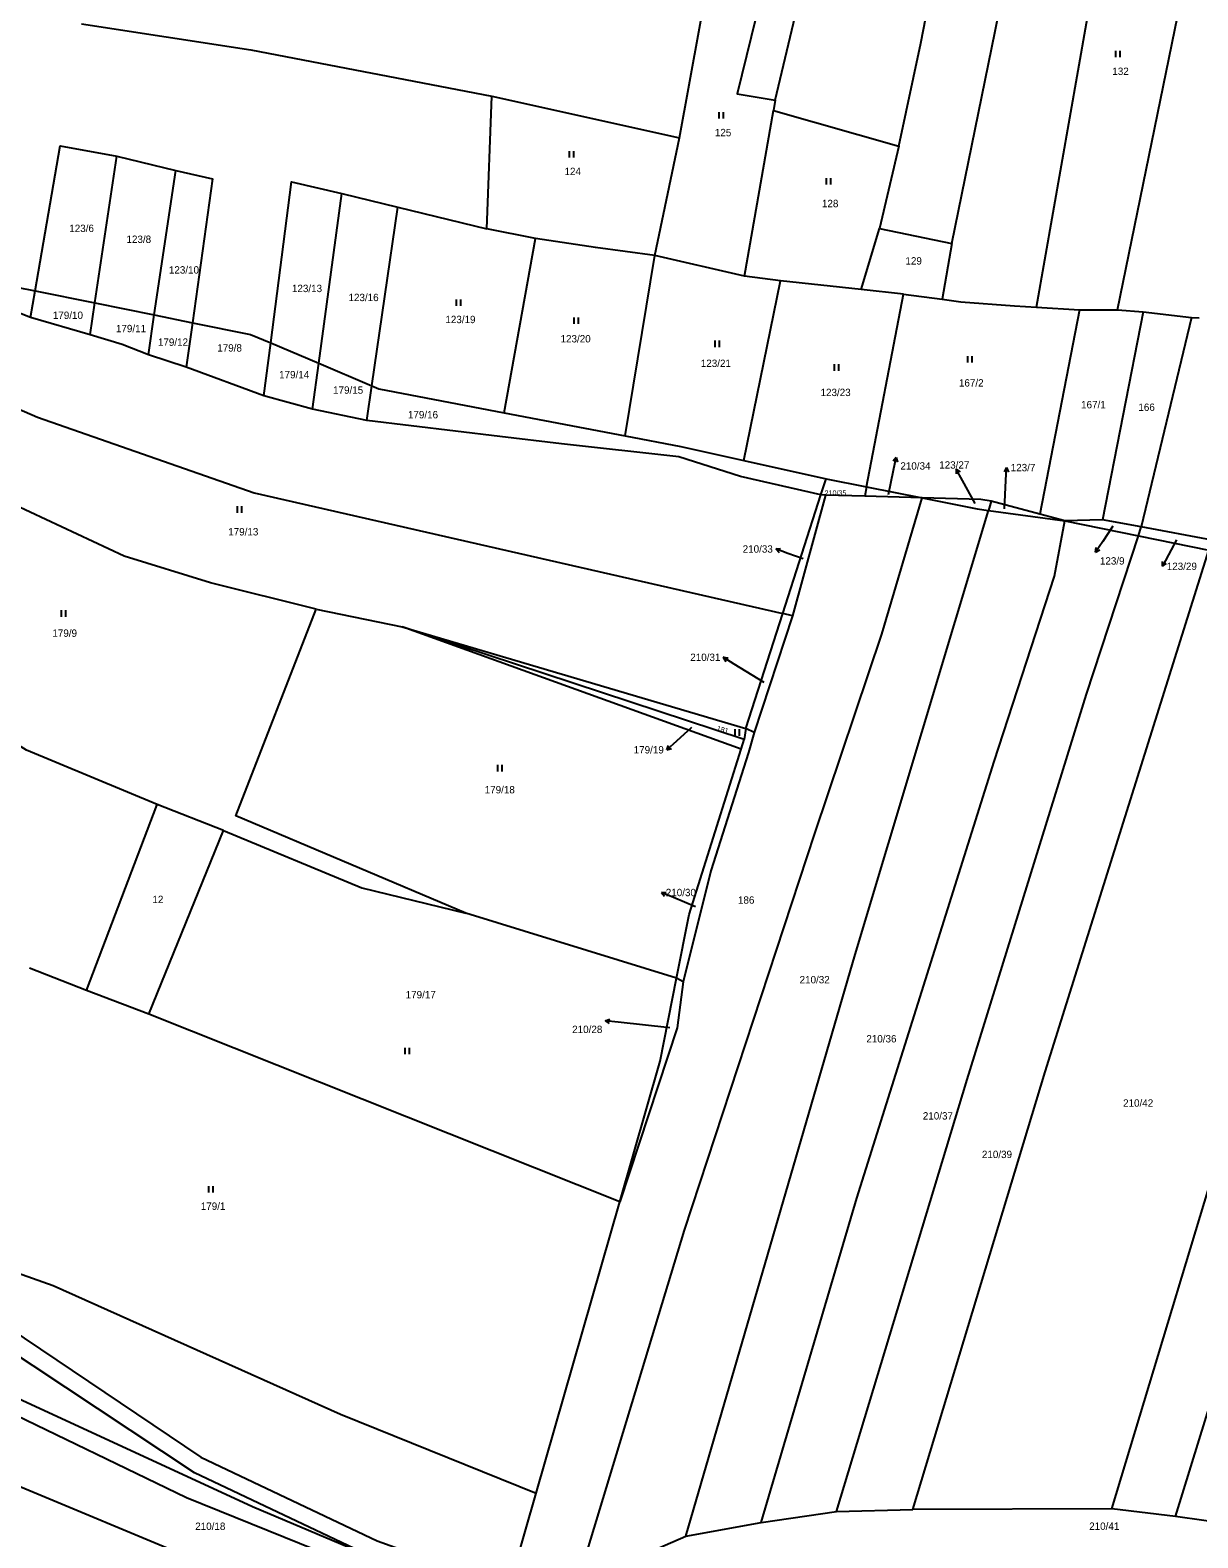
# Model space of a CAD drawing. Extents: x -746176 to -739709, y -1128407 to -1124482.
# Drawn here: x -742743.6 to -742474.2, y -1127693.8 to -1127345.9 of the extents above; entities that cross this region are included whole.
import ezdxf

# ---------------------------------------------------------------- set-up
doc = ezdxf.new("R2010")
doc.units = 0
for name, color, linetype in [('Vrstva 33', 7, 'Continuous'), ('Vrstva 42', 7, 'Continuous'), ('Vrstva 43', 7, 'Continuous'), ('Vrstva 44', 7, 'Continuous')]:
    doc.layers.add(name, color=color, linetype=linetype)

msp = doc.modelspace()

# ---------------------------------------------------------------- linework, layer by layer
at = {"layer": 'Vrstva 33'}
for p, q in [((-742638.23, -1127391.73), (-742637.04, -1127361.12)), ((-742637.04, -1127361.12), (-742593.77, -1127370.76)), ((-742578.78, -1127402.69), (-742572.09, -1127364.45)), ((-742571.73, -1127362.05), (-742572.09, -1127364.45)), ((-742572.09, -1127364.45), (-742543.19, -1127372.64)), ((-742599.43, -1127397.9), (-742593.77, -1127370.76)), ((-742728.68, -1127408.84), (-742723.61, -1127374.95)), ((-742723.61, -1127374.95), (-742709.98, -1127378.27)), ((-742543.19, -1127372.64), (-742547.67, -1127391.65)), ((-742714.95, -1127411.61), (-742709.98, -1127378.27)), ((-742677.01, -1127422.76), (-742671.68, -1127383.55)), ((-742671.68, -1127383.55), (-742658.73, -1127386.75)), ((-742664.74, -1127427.96), (-742658.73, -1127386.75)), ((-742658.73, -1127386.75), (-742638.23, -1127391.73)), ((-742626.99, -1127394), (-742638.23, -1127391.73)), ((-742551.9, -1127405.77), (-742547.67, -1127391.65)), ((-742547.67, -1127391.65), (-742530.91, -1127395.09)), ((-742634.26, -1127434.17), (-742626.99, -1127394)), ((-742530.91, -1127395.09), (-742533.18, -1127408)), ((-742743.5, -1127412.2), (-742776.69, -1127399.15)), ((-742776.69, -1127399.15), (-742742.44, -1127406.06)), ((-742606.32, -1127439.53), (-742599.43, -1127397.9)), ((-742578.78, -1127402.69), (-742599.43, -1127397.9)), ((-742570.47, -1127403.73), (-742578.78, -1127402.69)), ((-742743.5, -1127412.2), (-742742.44, -1127406.06)), ((-742742.44, -1127406.06), (-742728.68, -1127408.84)), ((-742578.95, -1127445.21), (-742570.47, -1127403.73)), ((-742551.9, -1127405.77), (-742570.47, -1127403.73)), ((-742542.09, -1127406.85), (-742551.9, -1127405.77)), ((-742550.64, -1127451.27), (-742542.09, -1127406.85)), ((-742542.09, -1127406.85), (-742533.18, -1127408)), ((-742729.77, -1127416.16), (-742728.68, -1127408.84)), ((-742728.68, -1127408.84), (-742714.95, -1127411.61)), ((-742511.41, -1127409.84), (-742501.5, -1127410.43)), ((-742501.5, -1127410.43), (-742510.66, -1127457.59)), ((-742501.5, -1127410.43), (-742492.74, -1127410.43)), ((-742492.74, -1127410.43), (-742486.8, -1127410.88)), ((-742729.77, -1127416.16), (-742743.5, -1127412.2)), ((-742716.31, -1127420.78), (-742714.95, -1127411.61)), ((-742714.95, -1127411.61), (-742706.16, -1127413.39)), ((-742706.16, -1127413.39), (-742707.61, -1127423.69)), ((-742486.8, -1127410.88), (-742496.21, -1127458.9)), ((-742475.67, -1127412.21), (-742487.24, -1127460.49)), ((-742486.8, -1127410.88), (-742475.67, -1127412.21)), ((-742475.67, -1127412.21), (-742473.87, -1127412.26)), ((-742707.61, -1127423.69), (-742716.31, -1127420.78)), ((-742689.66, -1127430.29), (-742688.08, -1127418.07)), ((-742688.08, -1127418.07), (-742677.01, -1127422.76)), ((-742689.66, -1127430.29), (-742707.61, -1127423.69)), ((-742678.44, -1127433.32), (-742677.01, -1127422.76)), ((-742677.01, -1127422.76), (-742664.74, -1127427.96)), ((-742678.44, -1127433.32), (-742689.66, -1127430.29)), ((-742665.91, -1127435.97), (-742664.74, -1127427.96)), ((-742665.91, -1127435.97), (-742678.44, -1127433.32)), ((-742634.26, -1127434.17), (-742606.32, -1127439.53)), ((-742578.95, -1127445.21), (-742559.94, -1127449.42)), ((-742561.14, -1127453.13), (-742559.94, -1127449.42)), ((-742559.94, -1127449.42), (-742550.64, -1127451.27)), ((-742550.64, -1127451.27), (-742551.05, -1127453.42)), ((-742550.64, -1127451.27), (-742537.81, -1127453.81)), ((-742569.95, -1127480.48), (-742561.14, -1127453.13)), ((-742560.06, -1127453.16), (-742567.73, -1127481)), ((-742560.06, -1127453.16), (-742561.14, -1127453.13)), ((-742551.05, -1127453.42), (-742560.06, -1127453.16)), ((-742537.81, -1127453.81), (-742551.05, -1127453.42)), ((-742521.86, -1127454.6), (-742522.49, -1127456.7)), ((-742510.66, -1127457.59), (-742521.86, -1127454.6)), ((-742522.49, -1127456.7), (-742504.84, -1127459.15)), ((-742504.84, -1127459.15), (-742510.66, -1127457.59)), ((-742496.21, -1127458.9), (-742504.84, -1127459.15)), ((-742504.84, -1127459.15), (-742487.9, -1127462.57)), ((-742487.24, -1127460.49), (-742496.21, -1127458.9)), ((-742487.9, -1127462.57), (-742487.24, -1127460.49)), ((-742487.9, -1127462.57), (-742471.63, -1127465.86)), ((-742470.92, -1127463.6), (-742487.24, -1127460.49)), ((-742677.58, -1127479.48), (-742657.78, -1127483.59)), ((-742578.5, -1127507.04), (-742569.95, -1127480.48)), ((-742567.73, -1127481), (-742576.53, -1127507.95)), ((-742567.73, -1127481), (-742569.95, -1127480.48)), ((-742657.78, -1127483.59), (-742578.5, -1127507.04)), ((-742579.56, -1127511.82), (-742657.78, -1127483.59)), ((-742578.86, -1127509.59), (-742657.78, -1127483.59)), ((-742578.5, -1127507.04), (-742578.86, -1127509.59)), ((-742576.53, -1127507.95), (-742578.5, -1127507.04)), ((-742579.56, -1127511.82), (-742578.86, -1127509.59)), ((-742730.61, -1127567.49), (-742714.26, -1127524.61)), ((-742699.01, -1127530.54), (-742714.26, -1127524.61)), ((-742716.21, -1127572.93), (-742699.01, -1127530.54)), ((-742594.44, -1127564.65), (-742643.07, -1127549.64)), ((-742730.61, -1127567.49), (-742743.76, -1127562.35)), ((-742592.94, -1127565.49), (-742594.44, -1127564.65)), ((-742716.21, -1127572.93), (-742730.61, -1127567.49)), ((-742607.54, -1127616.24), (-742716.21, -1127572.93)), ((-742626.86, -1127683.46), (-742607.54, -1127616.24)), ((-742632.48, -1127703.04), (-742626.86, -1127683.46)), ((-742574.91, -1127690.26), (-742557.53, -1127687.75)), ((-742557.53, -1127687.75), (-742539.98, -1127687.22)), ((-742494, -1127687.08), (-742539.98, -1127687.22)), ((-742479.32, -1127688.85), (-742494, -1127687.08)), ((-742592.33, -1127693.42), (-742574.91, -1127690.26)), ((-742464.41, -1127690.97), (-742479.32, -1127688.85)), ((-742617.34, -1127704.25), (-742592.33, -1127693.42))]:
    msp.add_line(p, q, dxfattribs=at)
for points in [[(-742571.73, -1127362.05), (-742565.58, -1127336.15), (-742554.25, -1127280.44), (-742551.83, -1127272.48)], [(-742543.19, -1127372.64), (-742538.11, -1127348.86), (-742526.83, -1127290.76), (-742523.05, -1127277.11)], [(-742530.91, -1127395.09), (-742510.84, -1127296.63), (-742506.04, -1127280.03)], [(-742511.41, -1127409.84), (-742497.94, -1127333.24), (-742489.37, -1127297.91), (-742486.41, -1127283.7)], [(-742492.74, -1127410.43), (-742471.55, -1127307.03), (-742467.25, -1127290.58)], [(-742593.77, -1127370.76), (-742586.78, -1127332.31), (-742583.12, -1127305.02)], [(-742582.72, -1127303.04), (-742570.71, -1127320.74), (-742580.44, -1127360.6), (-742571.73, -1127362.05)], [(-742731.72, -1127344.4), (-742692.68, -1127350.41), (-742637.04, -1127361.12)], [(-742742.44, -1127406.06), (-742736.64, -1127372.59), (-742723.61, -1127374.95)], [(-742709.98, -1127378.27), (-742701.49, -1127380.16), (-742706.16, -1127413.39)], [(-742688.08, -1127418.07), (-742683.29, -1127380.91), (-742671.68, -1127383.55)], [(-742599.43, -1127397.9), (-742613.15, -1127396.01), (-742626.99, -1127394)], [(-742533.18, -1127408), (-742528.9, -1127408.56), (-742516.49, -1127409.54), (-742511.41, -1127409.84)], [(-742706.16, -1127413.39), (-742692.72, -1127416.1), (-742688.08, -1127418.07)], [(-742716.31, -1127420.78), (-742722.38, -1127418.4), (-742729.77, -1127416.16)], [(-742782.56, -1127417.54), (-742741.92, -1127435.21), (-742691.94, -1127452.67), (-742569.95, -1127480.48)], [(-742664.74, -1127427.96), (-742663.18, -1127428.62), (-742634.26, -1127434.17)], [(-742677.58, -1127479.48), (-742701.98, -1127473.41), (-742721.92, -1127467.25), (-742790.61, -1127435.15)], [(-742561.14, -1127453.13), (-742579.7, -1127448.86), (-742593.95, -1127444.37), (-742621, -1127441.33), (-742635.25, -1127439.62), (-742665.91, -1127435.97)], [(-742606.32, -1127439.53), (-742593.44, -1127442), (-742578.95, -1127445.21)], [(-742617.34, -1127704.25), (-742592.59, -1127622.78), (-742562.59, -1127531.26), (-742547.11, -1127485.27), (-742537.81, -1127453.81)], [(-742521.86, -1127454.6), (-742524.23, -1127454.21), (-742537.81, -1127453.81)], [(-742537.81, -1127453.81), (-742525.12, -1127456.33), (-742522.49, -1127456.7)], [(-742592.33, -1127693.42), (-742553.24, -1127559.15), (-742522.49, -1127456.7)], [(-742574.91, -1127690.26), (-742552.84, -1127615.42), (-742521.15, -1127514.67), (-742507.28, -1127471.86), (-742504.84, -1127459.15)], [(-742557.53, -1127687.75), (-742527.44, -1127588.04), (-742499.87, -1127499.13), (-742487.9, -1127462.57)], [(-742539.98, -1127687.22), (-742509.38, -1127586.29), (-742471.63, -1127465.86)], [(-742494, -1127687.08), (-742463.97, -1127587.54), (-742428.89, -1127476.24)], [(-742643.07, -1127549.64), (-742696.11, -1127527.15), (-742677.58, -1127479.48)], [(-742479.32, -1127688.85), (-742461.68, -1127631.58), (-742415.87, -1127480.36)], [(-742714.26, -1127524.61), (-742744.44, -1127512), (-742789.88, -1127483.77)], [(-742576.53, -1127507.95), (-742577.87, -1127512.58), (-742586.52, -1127539.9), (-742592.94, -1127565.49)], [(-742594.44, -1127564.65), (-742591.53, -1127549.93), (-742579.56, -1127511.82)], [(-742699.01, -1127530.54), (-742667.09, -1127543.83), (-742643.07, -1127549.64)], [(-742607.54, -1127616.24), (-742598.22, -1127583.8), (-742594.44, -1127564.65)], [(-742592.94, -1127565.49), (-742594.28, -1127576.09), (-742607.54, -1127616.24)], [(-742842.01, -1127594.12), (-742781.53, -1127620.27), (-742738.25, -1127635.58), (-742671.97, -1127665.27), (-742626.86, -1127683.46)], [(-742849.54, -1127613.47), (-742848.76, -1127613.6), (-742786.4, -1127635.17), (-742756.11, -1127640.29), (-742704.21, -1127675.14), (-742663.56, -1127694.46), (-742647.49, -1127700.26), (-742632.48, -1127703.04)], [(-742664.42, -1127698.33), (-742705.7, -1127678.8), (-742757.77, -1127644.27), (-742759.53, -1127644.48)], [(-742763.36, -1127654.17), (-742748.4, -1127660.64), (-742692.32, -1127686.56), (-742664.42, -1127698.33)], [(-742640.13, -1127711.82), (-742707.48, -1127684.6), (-742751.48, -1127663.32), (-742764.73, -1127657.63)], [(-742643.36, -1127725.63), (-742711.98, -1127696.17), (-742770.35, -1127671.87)]]:
    msp.add_lwpolyline(points, dxfattribs=at)
at = {"layer": 'Vrstva 43'}
for p, q in [((-742543.8, -1127444.48), (-742544.49, -1127445.35)), ((-742544.42, -1127447.41), (-742543.8, -1127444.48)), ((-742543.8, -1127444.48), (-742543.51, -1127445.56)), ((-742545.56, -1127453.02), (-742544.42, -1127447.41)), ((-742528.52, -1127449.81), (-742529.97, -1127447.19)), ((-742529.97, -1127447.19), (-742529.05, -1127447.82)), ((-742529.97, -1127447.19), (-742529.93, -1127448.3)), ((-742518.34, -1127446.83), (-742518.9, -1127447.81)), ((-742518.5, -1127449.83), (-742518.34, -1127446.83)), ((-742518.34, -1127446.83), (-742517.9, -1127447.86)), ((-742525.6, -1127455.12), (-742528.52, -1127449.81)), ((-742518.79, -1127456.34), (-742518.5, -1127449.83)), ((-742493.78, -1127460.36), (-742496.13, -1127463.88)), ((-742571.59, -1127465.59), (-742570.48, -1127465.47)), ((-742568.77, -1127466.62), (-742571.59, -1127465.59)), ((-742571.59, -1127465.59), (-742570.82, -1127466.41)), ((-742496.13, -1127463.88), (-742497.81, -1127466.37)), ((-742497.81, -1127466.37), (-742497.66, -1127465.26)), ((-742497.81, -1127466.37), (-742496.83, -1127465.82)), ((-742479.13, -1127463.5), (-742480.96, -1127466.96)), ((-742565.23, -1127467.88), (-742568.77, -1127466.62)), ((-742480.96, -1127466.96), (-742482.37, -1127469.61)), ((-742482.37, -1127469.61), (-742482.34, -1127468.49)), ((-742482.37, -1127469.61), (-742481.46, -1127468.96)), ((-742581.13, -1127492.18), (-742583.68, -1127490.59)), ((-742583.68, -1127490.59), (-742582.56, -1127490.7)), ((-742583.68, -1127490.59), (-742583.09, -1127491.54)), ((-742574.26, -1127496.44), (-742581.13, -1127492.18)), ((-742590.98, -1127506.8), (-742594.5, -1127509.95)), ((-742594.5, -1127509.95), (-742596.73, -1127511.96)), ((-742596.73, -1127511.96), (-742596.32, -1127510.92)), ((-742596.73, -1127511.96), (-742595.65, -1127511.66)), ((-742597.94, -1127544.88), (-742596.83, -1127544.81)), ((-742595.18, -1127546.05), (-742597.94, -1127544.88)), ((-742597.94, -1127544.88), (-742597.22, -1127545.73)), ((-742590.09, -1127548.19), (-742595.18, -1127546.05)), ((-742610.93, -1127574.5), (-742609.88, -1127574.1)), ((-742607.94, -1127574.81), (-742610.93, -1127574.5)), ((-742610.93, -1127574.5), (-742609.98, -1127575.1)), ((-742596.01, -1127576.14), (-742607.94, -1127574.81))]:
    msp.add_line(p, q, dxfattribs=at)
at = {"layer": 'Vrstva 44'}
for p, q in [((-742493.1, -1127352.13), (-742493.1, -1127350.63)), ((-742492.1, -1127352.13), (-742492.1, -1127350.63)), ((-742584.6, -1127366.28), (-742584.6, -1127364.78)), ((-742583.6, -1127366.28), (-742583.6, -1127364.78)), ((-742619.18, -1127375.28), (-742619.18, -1127373.78)), ((-742618.18, -1127375.28), (-742618.18, -1127373.78)), ((-742559.87, -1127381.51), (-742559.87, -1127380.01)), ((-742558.87, -1127381.51), (-742558.87, -1127380.01)), ((-742645.22, -1127409.53), (-742645.22, -1127408.03)), ((-742644.22, -1127409.53), (-742644.22, -1127408.03)), ((-742618.06, -1127413.66), (-742618.06, -1127412.16)), ((-742617.06, -1127413.66), (-742617.06, -1127412.16)), ((-742585.52, -1127419.01), (-742585.52, -1127417.51)), ((-742584.52, -1127419.01), (-742584.52, -1127417.51)), ((-742558.05, -1127424.5), (-742558.05, -1127423)), ((-742557.05, -1127424.5), (-742557.05, -1127423)), ((-742527.22, -1127422.61), (-742527.22, -1127421.11)), ((-742526.22, -1127422.61), (-742526.22, -1127421.11)), ((-742695.72, -1127457.24), (-742695.72, -1127455.74)), ((-742694.72, -1127457.24), (-742694.72, -1127455.74)), ((-742736.33, -1127481.24), (-742736.33, -1127479.74)), ((-742735.33, -1127481.24), (-742735.33, -1127479.74)), ((-742580.97, -1127508.69), (-742580.97, -1127507.19)), ((-742579.97, -1127508.69), (-742579.97, -1127507.19)), ((-742635.71, -1127516.94), (-742635.71, -1127515.44)), ((-742634.71, -1127516.94), (-742634.71, -1127515.44)), ((-742657.03, -1127582.2), (-742657.03, -1127580.7)), ((-742656.03, -1127582.2), (-742656.03, -1127580.7)), ((-742702.33, -1127614.12), (-742702.33, -1127612.62)), ((-742701.33, -1127614.12), (-742701.33, -1127612.62))]:
    msp.add_line(p, q, dxfattribs=at)

# ---------------------------------------------------------------- texts
at = {"layer": 'Vrstva 42'}
for s, height, p in [('132', 1.7, (-742493.92, -1127356.23)), ('125', 1.7, (-742585.62, -1127370.37)), ('124', 1.7, (-742620.31, -1127379.33)), ('128', 1.7, (-742560.91, -1127386.74)), ('123/6', 1.7, (-742734.56, -1127392.47)), ('123/8', 1.7, (-742721.36, -1127394.99)), ('129', 1.7, (-742541.65, -1127399.98)), ('123/10', 1.7, (-742711.58, -1127402.06)), ('123/13', 1.7, (-742683.19, -1127406.34)), ('123/16', 1.7, (-742670.14, -1127408.42)), ('179/10', 1.7, (-742738.35, -1127412.53)), ('179/11', 1.7, (-742723.79, -1127415.59)), ('123/19', 1.7, (-742647.79, -1127413.5)), ('179/12', 1.7, (-742714.11, -1127418.73)), ('123/20', 1.7, (-742621.22, -1127417.95)), ('179/8', 1.7, (-742700.42, -1127420.06)), ('123/21', 1.7, (-742588.86, -1127423.61)), ('179/14', 1.7, (-742686.15, -1127426.23)), ('167/2', 1.7, (-742529.31, -1127428.13)), ('179/15', 1.7, (-742673.7, -1127429.79)), ('123/23', 1.7, (-742561.24, -1127430.33)), ('167/1', 1.7, (-742501.13, -1127433.16)), ('179/16', 1.7, (-742656.43, -1127435.47)), ('166', 1.7, (-742487.91, -1127433.75)), ('123/27', 1.7, (-742533.86, -1127447.07)), ('210/34', 1.7, (-742542.82, -1127447.3)), ('123/7', 1.7, (-742517.36, -1127447.68)), ('210/35', 1.19, (-742560.3, -1127453.27)), ('179/13', 1.7, (-742697.89, -1127462.49)), ('210/33', 1.7, (-742579.2, -1127466.46)), ('123/9', 1.7, (-742496.79, -1127469.21)), ('123/29', 1.7, (-742481.36, -1127470.46)), ('179/9', 1.7, (-742738.46, -1127485.88)), ('210/31', 1.7, (-742591.29, -1127491.45)), ('179/19', 1.7, (-742604.35, -1127512.8)), ('179/18', 1.7, (-742638.72, -1127522.01)), ('12', 1.7, (-742715.38, -1127547.33)), ('210/30', 1.7, (-742596.94, -1127545.73)), ('186', 1.7, (-742580.29, -1127547.47)), ('210/32', 1.7, (-742566.07, -1127565.85)), ('179/17', 1.7, (-742656.95, -1127569.3)), ('210/28', 1.7, (-742618.53, -1127577.31)), ('210/36', 1.7, (-742550.67, -1127579.48)), ('210/42', 1.7, (-742491.44, -1127594.3)), ('210/37', 1.7, (-742537.64, -1127597.27)), ('210/39', 1.7, (-742524.01, -1127606.16)), ('179/1', 1.7, (-742704.22, -1127618.11)), ('210/18', 1.7, (-742705.5, -1127691.97)), ('210/41', 1.7, (-742499.26, -1127691.95))]:
    msp.add_text(s, height=height, dxfattribs=at).set_placement(p)
msp.add_text('181', height=1.19, rotation=345, dxfattribs=at).set_placement((-742585.29, -1127507.52))

doc.saveas('drawing.dxf')
